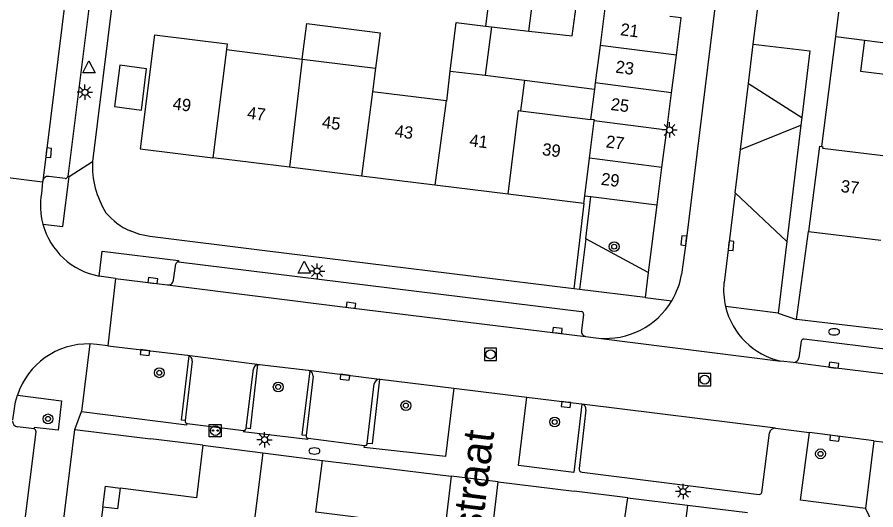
# Model space of a CAD drawing. Extents: x 131000 to 133014, y 396499 to 399001.
# Drawn here: x 131752.2 to 131822, y 397186.5 to 397226.6 of the extents above; entities that cross this region are included whole.
import ezdxf

# ---------------------------------------------------------------- set-up
doc = ezdxf.new("R2010")
doc.units = 0
for name, color, linetype in [('gg-afsc-erfafscheiding', 7, 'Continuous'), ('gg-afsc-muur', 7, 'Continuous'), ('gg-anno-huisnummerreeks BGT', 7, 'Continuous'), ('gg-anno-openbare ruimte label', 7, 'Continuous'), ('gg-bbg-bijgebouw', 7, 'Continuous'), ('gg-bbg-gedigitaliseerde bebouwing', 7, 'Continuous'), ('gg-bbg-gedigitaliseerde bijgebouw', 7, 'Continuous'), ('gg-bbg-hoofdgebouw', 7, 'Continuous'), ('gg-bbg-luifel en loopbrug', 7, 'Continuous'), ('gg-bbg-tussenscheiding', 7, 'Continuous'), ('gg-knt-verharding', 7, 'Continuous'), ('gg-knt-verharding nz', 7, 'Continuous'), ('gt-grn-groengrens', 7, 'Continuous'), ('gt-grn-weggrens', 7, 'Continuous'), ('gt-symb-boom', 7, 'Continuous'), ('gt-symb-brandkraan', 7, 'Continuous'), ('gt-symb-kolk', 7, 'Continuous'), ('gt-symb-laadpunt elektrisch vervoer', 7, 'Continuous'), ('gt-symb-lichtmast', 7, 'Continuous'), ('gt-symb-rioolschacht', 7, 'Continuous'), ('gt-symb-waterafsluiter', 7, 'Continuous')]:
    doc.layers.add(name, color=color, linetype=linetype)

# ---------------------------------------------------------------- blocks, each defined once
blk = doc.blocks.new('gt0-LMAST')
at = {"layer": 'gt-symb-lichtmast'}
for p, q in [((-0.182, 0.173), (-0.447, 0.438)), ((-0.005, 0.246), (-0.005, 0.621)), ((0.172, 0.173), (0.437, 0.438)), ((-0.255, -0.004), (-0.63, -0.004)), ((-0.182, -0.181), (-0.447, -0.446)), ((-0.005, -0.254), (-0.005, -0.629)), ((0.437, -0.446), (0.172, -0.181)), ((0.245, -0.004), (0.62, -0.004))]:
    blk.add_line(p, q, dxfattribs=at)
blk.add_circle((-0.005, -0.004), 0.25, dxfattribs=at)
blk = doc.blocks.new('gt0-BOOM')
at = {"layer": 'gt-symb-boom'}
for radius in [0.4, 0.2]:
    blk.add_circle((0, 0), radius, dxfattribs=at)
blk = doc.blocks.new('gt0-KOLK')
at = {"layer": 'gt-symb-kolk'}
blk.add_lwpolyline([(0, 0), (0.375, 0), (0.375, 0.4), (-0.375, 0.4), (-0.375, 0), (0, 0)], dxfattribs=at)
blk = doc.blocks.new('gt0-WAFSL')
at = {"layer": 'gt-symb-waterafsluiter'}
for p, q in [((-0.5, -0.333), (0, 0.667)), ((0, 0.667), (0.5, -0.333)), ((0.5, -0.333), (-0.5, -0.333))]:
    blk.add_line(p, q, dxfattribs=at)
blk = doc.blocks.new('gt0-BR')
at = {"layer": 'gt-symb-brandkraan'}
for centre, radius, start, end in [((-0.244, 0), 0.206, 107.56694, 252.43307), ((0.599, -2.664), 3, 106.89205, 107.56694), ((0, -0.691), 0.938, 73.10799, 106.89205), ((-0.599, -2.664), 3, 72.43309, 73.10799), ((0.244, 0), 0.206, 287.56695, 72.43309), ((0.599, 2.664), 3, 252.43307, 253.10797), ((0, 0.691), 0.938, 253.10797, 286.89206), ((-0.599, 2.664), 3, 286.89206, 287.56695)]:
    blk.add_arc(centre, radius, start, end, dxfattribs=at)
blk = doc.blocks.new('gt0-RS')
at = {"layer": 'gt-symb-rioolschacht'}
blk.add_lwpolyline([(-0.5, -0.5), (0.5, -0.5), (0.5, 0.5), (-0.5, 0.5)], close=True, dxfattribs=at)
blk.add_circle((0, 0), 0.375, dxfattribs=at)
blk = doc.blocks.new('gt0-LEV')
at = {"layer": 'gt-symb-laadpunt elektrisch vervoer'}
blk.add_lwpolyline([(-0.486, 0.501), (0.486, 0.501), (0.486, -0.499), (-0.486, -0.499)], close=True, dxfattribs=at)
for centre, radius in [((0, 0), 0.393), ((-0.186, 0), 0.0566), ((0.186, 0), 0.0566)]:
    blk.add_circle(centre, radius, dxfattribs=at)

msp = doc.modelspace()

# ---------------------------------------------------------------- linework, layer by layer
at = {"layer": 'gg-afsc-erfafscheiding'}
for p, q in [((131755.841, 397184.423), (131756.9, 397193.04)), ((131756.9, 397193.04), (131763.042, 397192.285)), ((131781.308, 397190.005), (131787.51, 397189.25)), ((131787.51, 397189.25), (131786.966, 397184.698)), ((131789.761, 397175.826), (131791.33, 397188.77)), ((131791.33, 397188.77), (131797.503, 397188.017))]:
    msp.add_line(p, q, dxfattribs=at)
at = {"layer": 'gg-afsc-muur'}
for p, q in [((131817.644, 397216.073), (131818.795, 397225.028)), ((131818.795, 397225.028), (131821.111, 397224.728)), ((131767.31, 397191.76), (131763.042, 397192.285)), ((131777.04, 397190.53), (131781.308, 397190.005)), ((131801.87, 397187.48), (131797.503, 397188.017))]:
    msp.add_line(p, q, dxfattribs=at)
at = {"layer": 'gg-bbg-bijgebouw'}
for p, q in [((131797.352, 397225.082), (131797.669, 397227.482)), ((131821.111, 397224.728), (131820.795, 397222.219)), ((131821.111, 397224.728), (131824.661, 397224.291))]:
    msp.add_line(p, q, dxfattribs=at)
at = {"layer": 'gg-bbg-gedigitaliseerde bebouwing'}
for p, q in [((131769.22, 397223.97), (131775.392, 397223.196)), ((131775.392, 397223.196), (131781.353, 397222.449)), ((131781.353, 397222.449), (131781.114, 397220.538)), ((131787.094, 397219.788), (131781.114, 397220.538)), ((131787.143, 397219.783), (131787.094, 397219.788))]:
    msp.add_line(p, q, dxfattribs=at)
msp.add_lwpolyline([(131763.38, 397225.17), (131769.277, 397224.433), (131769.22, 397223.97)], dxfattribs=at)
at = {"layer": 'gg-bbg-gedigitaliseerde bijgebouw'}
for p, q in [((131790.62, 397228.473), (131790.295, 397225.882)), ((131790.295, 397225.882), (131790.775, 397225.828)), ((131790.775, 397225.828), (131793.83, 397225.481)), ((131793.83, 397225.481), (131797.352, 397225.082)), ((131820.795, 397222.219), (131824.352, 397221.781))]:
    msp.add_line(p, q, dxfattribs=at)
msp.add_lwpolyline([(131762.309, 397219.045), (131762.738, 397222.415), (131760.561, 397222.693), (131760.132, 397219.323), (131762.309, 397219.045)], dxfattribs=at)
at = {"layer": 'gg-bbg-hoofdgebouw'}
for p, q in [((131800.011, 397227.348), (131799.619, 397224.305)), ((131806.219, 397226.548), (131805.279, 397226.669)), ((131805.827, 397223.505), (131806.219, 397226.548)), ((131799.619, 397224.305), (131799.227, 397221.261)), ((131805.435, 397220.461), (131805.827, 397223.505)), ((131787.143, 397219.783), (131787.414, 397222.225)), ((131787.414, 397222.225), (131790.271, 397221.874)), ((131790.271, 397221.874), (131793.467, 397221.481)), ((131793.467, 397221.481), (131793.146, 397218.985)), ((131799.227, 397221.261), (131799.162, 397220.755)), ((131799.162, 397220.755), (131798.842, 397218.277)), ((131805.042, 397217.418), (131805.435, 397220.461)), ((131793.146, 397218.985), (131798.842, 397218.277)), ((131804.65, 397214.374), (131805.042, 397217.418)), ((131817.45, 397216.098), (131816.58, 397209.17)), ((131817.45, 397216.098), (131817.644, 397216.073)), ((131774.358, 397214.39), (131768.117, 397215.161)), ((131780.208, 397213.666), (131774.358, 397214.39)), ((131804.258, 397211.331), (131804.65, 397214.374)), ((131786.187, 397212.927), (131780.208, 397213.666)), ((131792.147, 397212.191), (131786.187, 397212.927)), ((131798.3, 397211.43), (131792.147, 397212.191)), ((131798.3, 397211.43), (131798.38, 397212.07)), ((131798.38, 397212.07), (131798.877, 397212.008)), ((131798.877, 397212.008), (131804.223, 397211.335)), ((131804.223, 397211.335), (131804.258, 397211.331)), ((131816.58, 397209.17), (131822.45, 397208.447)), ((131767.31, 397191.76), (131772.175, 397191.145)), ((131772.175, 397191.145), (131777.04, 397190.53)), ((131801.87, 397187.48), (131806.735, 397186.88)), ((131759.17, 397186.72), (131758.844, 397184.128)), ((131806.735, 397186.88), (131811.6, 397186.28))]:
    msp.add_line(p, q, dxfattribs=at)
for points in [[(131763.38, 397225.17), (131762.22, 397215.89), (131768.117, 397215.161)], [(131817.644, 397216.073), (131817.722, 397216.063), (131817.709, 397215.956), (131823.299, 397215.266)], [(131767.31, 397191.76), (131766.78, 397187.49), (131760.57, 397188.27)], [(131782.77, 397185.53), (131776.51, 397186.32), (131777.04, 397190.53)], [(131760.57, 397188.27), (131760.36, 397186.57), (131759.17, 397186.72)], [(131795.1, 397184.01), (131801.25, 397183.25), (131801.87, 397187.48)]]:
    msp.add_lwpolyline(points, dxfattribs=at)
at = {"layer": 'gg-bbg-luifel en loopbrug'}
for p, q in [((131790.775, 397225.828), (131790.271, 397221.874)), ((131793.467, 397221.481), (131799.162, 397220.755))]:
    msp.add_line(p, q, dxfattribs=at)
for points in [[(131775.392, 397223.196), (131775.76, 397226.082), (131781.719, 397225.323), (131781.353, 397222.449)], [(131787.414, 397222.225), (131787.919, 397226.185), (131790.295, 397225.882)], [(131759.17, 397186.72), (131759.384, 397188.419), (131760.57, 397188.27)]]:
    msp.add_lwpolyline(points, dxfattribs=at)
at = {"layer": 'gg-bbg-tussenscheiding'}
for p, q in [((131793.83, 397225.481), (131794.15, 397228.031)), ((131769.22, 397223.97), (131768.117, 397215.161)), ((131805.827, 397223.505), (131799.619, 397224.305)), ((131775.392, 397223.196), (131774.358, 397214.39)), ((131805.435, 397220.461), (131799.227, 397221.261)), ((131781.114, 397220.538), (131780.208, 397213.666)), ((131787.094, 397219.788), (131786.187, 397212.927)), ((131798.765, 397215.133), (131799.148, 397218.177)), ((131805.042, 397217.418), (131799.148, 397218.177)), ((131798.38, 397212.07), (131798.765, 397215.133)), ((131804.65, 397214.374), (131798.765, 397215.133)), ((131772.175, 397191.145), (131771.117, 397182.569)), ((131806.735, 397186.88), (131805.672, 397178.327))]:
    msp.add_line(p, q, dxfattribs=at)
for points in [[(131792.147, 397212.191), (131792.992, 397219.004), (131793.146, 397218.985)], [(131799.148, 397218.177), (131799.155, 397218.238), (131798.842, 397218.277)]]:
    msp.add_lwpolyline(points, dxfattribs=at)
at = {"layer": 'gg-knt-verharding'}
for p, q in [((131760.493, 397232.282), (131758.333, 397214.867)), ((131758.562, 397231.547), (131756.324, 397213.643)), ((131811.683, 397221.202), (131812.077, 397224.416)), ((131811.026, 397215.841), (131811.683, 397221.202)), ((131816.019, 397218.431), (131815.946, 397217.826)), ((131815.946, 397217.826), (131814.804, 397208.347)), ((131810.593, 397212.309), (131811.026, 397215.841)), ((131748.783, 397213.872), (131754.277, 397213.202)), ((131754.288, 397213.286), (131754.277, 397213.202)), ((131756.116, 397213.481), (131754.774, 397213.644)), ((131756.432, 397213.629), (131756.324, 397213.643)), ((131754.277, 397213.202), (131754.176, 397212.255)), ((131810.593, 397212.309), (131809.695, 397204.996)), ((131798.3, 397211.43), (131797.48, 397204.5)), ((131804.223, 397211.335), (131803.529, 397205.827)), ((131815.58, 397201.99), (131816.58, 397209.17)), ((131814.804, 397208.347), (131814.101, 397202.505)), ((131764.92, 397205.19), (131765.116, 397206.521)), ((131765.329, 397206.701), (131798.1, 397202.647)), ((131803.529, 397205.827), (131803.277, 397203.785)), ((131760.217, 397205.346), (131758.874, 397205.527)), ((131760.217, 397205.346), (131759.57, 397199.859)), ((131760.217, 397205.346), (131764.438, 397204.81)), ((131797.936, 397204.444), (131797.48, 397204.5)), ((131803.277, 397203.785), (131797.936, 397204.444)), ((131814.101, 397202.505), (131809.822, 397203.044)), ((131798.27, 397202.417), (131798.1, 397201.088)), ((131851.75, 397197.76), (131815.58, 397201.99)), ((131758.122, 397200.004), (131757.438, 397194.509)), ((131798.425, 397200.621), (131799.484, 397200.479)), ((131815.981, 397200.223), (131815.79, 397198.886)), ((131848.037, 397196.445), (131816.213, 397200.389)), ((131759.57, 397199.859), (131766.05, 397199.096)), ((131766.45, 397198.615), (131765.872, 397193.769)), ((131766.05, 397199.096), (131766.208, 397199.043)), ((131815.312, 397198.494), (131814.315, 397198.615)), ((131770.824, 397193.136), (131771.428, 397197.966)), ((131771.764, 397198.338), (131771.91, 397198.345)), ((131771.91, 397198.345), (131775.872, 397197.874)), ((131776.274, 397197.379), (131775.698, 397192.539)), ((131775.872, 397197.874), (131776.028, 397197.822)), ((131780.681, 397191.912), (131781.233, 397196.755)), ((131787.715, 397196.4), (131793.665, 397195.668)), ((131798.465, 397194.63), (131797.922, 397189.872)), ((131753.58, 397193.102), (131752.228, 397193.257)), ((131766.021, 397193.527), (131770.608, 397192.947)), ((131813.879, 397193.151), (131816.638, 397192.796)), ((131750.152, 397164.03), (131753.744, 397192.853)), ((131775.868, 397192.322), (131780.457, 397191.741)), ((131812.771, 397187.919), (131813.393, 397192.76)), ((131821.893, 397192.131), (131816.638, 397192.796)), ((131821.893, 397192.131), (131821.202, 397186.616)), ((131821.893, 397192.131), (131827.009, 397191.489)), ((131798.163, 397189.554), (131812.56, 397187.758))]:
    msp.add_line(p, q, dxfattribs=at)
for points in [[(131809.227, 397229.593), (131806.623, 397208.399), (131806.25, 397205.671)], [(131812.077, 397224.416), (131812.655, 397229.14), (131812.656, 397229.144)], [(131812.077, 397224.416), (131816.674, 397223.87), (131816.019, 397218.431)], [(131754.298, 397209.764), (131755.909, 397209.555), (131756.432, 397213.629)], [(131797.48, 397204.5), (131772.341, 397207.599), (131763, 397208.75), (131762.175, 397208.915), (131761.385, 397209.203)], [(131758.874, 397205.527), (131759.11, 397207.56), (131765.341, 397206.798), (131765.329, 397206.701)], [(131759.57, 397199.859), (131758.682, 397199.964), (131758.122, 397200.004)], [(131765.872, 397193.769), (131765.579, 397193.804), (131766.208, 397199.043)], [(131771.764, 397198.338), (131771.143, 397193.098), (131770.824, 397193.136)], [(131775.698, 397192.539), (131775.399, 397192.575), (131776.028, 397197.822)], [(131781.684, 397197.139), (131781.089, 397191.866), (131780.681, 397191.912)], [(131781.684, 397197.139), (131781.735, 397197.136), (131787.715, 397196.4)], [(131751.843, 397193.824), (131751.978, 397194.749), (131752.077, 397195.302), (131752.227, 397195.843)], [(131752.227, 397195.843), (131755.807, 397195.378), (131755.554, 397192.992), (131753.591, 397193.199), (131753.58, 397193.102)], [(131787.715, 397196.4), (131787.03, 397190.838), (131780.44, 397191.589), (131780.457, 397191.741)], [(131798.136, 397195.116), (131797.476, 397189.55), (131792.981, 397190.106), (131793.665, 397195.668)], [(131793.665, 397195.668), (131798.096, 397195.123), (131798.136, 397195.116)], [(131757.438, 397194.509), (131766.009, 397193.43), (131766.021, 397193.527)], [(131770.608, 397192.947), (131770.6, 397192.878), (131775.859, 397192.248), (131775.868, 397192.322)], [(131821.202, 397186.616), (131815.929, 397187.288), (131816.638, 397192.796)]]:
    msp.add_lwpolyline(points, dxfattribs=at)
for centre, radius, start, end in [((131765.524, 397214.523), 7.199, 177.26186, 212.16855), ((131754.714, 397213.216), 0.432, 82.02931, 170.72331), ((131756.141, 397213.664), 0.184, 262.29692, 353.52929), ((131759.958, 397211.29), 5.862, 170.52282, 195.08497), ((131763.681, 397214.251), 5.545, 219.9477, 245.53806), ((131759.961, 397211.29), 5.865, 195.08405, 259.32164), ((131765.341, 397206.471), 0.23, 92.97123, 167.4291), ((131800.054, 397206.744), 6.288, 329.1228, 350.17376), ((131764.49, 397205.239), 0.432, 263.04042, 353.46279), ((131815.563, 397204.398), 5.899, 174.17807, 193.26693), ((131800.05, 397206.747), 6.293, 264.84161, 329.12273), ((131815.59, 397204.402), 5.926, 193.24901, 257.57298), ((131798.099, 397202.468), 0.179, 343.40552, 89.53295), ((131798.5, 397201.02), 0.406, 170.33918, 259.33136), ((131757.977, 397193.954), 6.052, 88.62289, 161.81001), ((131816.186, 397200.181), 0.21, 82.69129, 168.47745), ((131765.983, 397198.633), 0.468, 357.7687, 61.20072), ((131815.346, 397198.939), 0.447, 265.57499, 353.13425), ((131771.855, 397197.918), 0.429, 102.20717, 173.61451), ((131775.8, 397197.405), 0.475, 356.81948, 61.26776), ((131781.707, 397196.655), 0.485, 92.75836, 168.06652), ((131798.04, 397194.696), 0.43, 351.11962, 77.07283), ((131752.33, 397193.745), 0.498, 179.63699, 258.13656), ((131766.069, 397193.723), 0.202, 166.93312, 256.3083), ((131753.464, 397192.847), 0.28, 1.19737, 65.54319), ((131770.639, 397193.129), 0.185, 260.2822, 2.08965), ((131813.871, 397192.664), 0.487, 89.03865, 168.59657), ((131775.892, 397192.516), 0.195, 173.1411, 263.00992), ((131780.503, 397191.913), 0.178, 255.04641, 359.6693), ((131798.189, 397189.824), 0.271, 169.8404, 264.47378), ((131812.583, 397187.947), 0.19, 263.13507, 351.5546)]:
    msp.add_arc(centre, radius, start, end, dxfattribs=at)
at = {"layer": 'gg-knt-verharding nz'}
for p, q in [((131756.665, 397232.415), (131754.288, 397213.286)), ((131766.05, 397199.096), (131771.91, 397198.345)), ((131775.872, 397197.874), (131781.684, 397197.139)), ((131813.879, 397193.151), (131798.136, 397195.116))]:
    msp.add_line(p, q, dxfattribs=at)
for points in [[(131819, 397227.02), (131818.751, 397225.034), (131818.795, 397225.028)], [(131764.438, 397204.81), (131779.336, 397202.957), (131798.425, 397200.621)], [(131848.404, 397194.374), (131835.663, 397195.97), (131818.606, 397198.073), (131815.312, 397198.494)]]:
    msp.add_lwpolyline(points, dxfattribs=at)
at = {"layer": 'gt-grn-groengrens'}
for p, q in [((131811.683, 397221.202), (131816.019, 397218.431)), ((131811.026, 397215.841), (131815.946, 397217.826)), ((131798.445, 397208.572), (131798.877, 397212.008)), ((131814.804, 397208.347), (131810.593, 397212.309)), ((131798.445, 397208.572), (131797.936, 397204.444)), ((131803.529, 397205.827), (131798.445, 397208.572))]:
    msp.add_line(p, q, dxfattribs=at)
at = {"layer": 'gt-grn-weggrens'}
for p, q in [((131756.432, 397213.629), (131758.333, 397214.867)), ((131803.277, 397203.785), (131805.451, 397203.517)), ((131814.101, 397202.505), (131815.58, 397201.99)), ((131799.484, 397200.479), (131814.315, 397198.615)), ((131756.9, 397193.04), (131757.438, 397194.509)), ((131791.33, 397188.77), (131787.51, 397189.25)), ((131821.202, 397186.616), (131822, 397184.96))]:
    msp.add_line(p, q, dxfattribs=at)

# ---------------------------------------------------------------- block references
at = {"layer": 'gt-symb-boom'}
for p in [(131800.762, 397207.93), (131763.768, 397197.66), (131773.437, 397196.507), (131783.82, 397194.99), (131754.713, 397193.904), (131795.92, 397193.649), (131817.542, 397191.062)]:
    msp.add_blockref('gt0-BOOM', p, dxfattribs=at)
at = {"layer": 'gt-symb-brandkraan'}
for p in [(131818.649, 397200.993), (131776.382, 397191.288)]:
    msp.add_blockref('gt0-BR', p, dxfattribs=at)
at = {"layer": 'gt-symb-kolk'}
for p, rotation in [((131754.574, 397215.595), -95.99886832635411), ((131806.623, 397208.399), 84.00113167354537), ((131810.068, 397208.019), -95.99886832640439), ((131763.214, 397204.965), -6.997895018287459), ((131779.336, 397202.957), -6.9978950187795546), ((131796.121, 397200.903), -6.9978950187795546), ((131762.627, 397199.499), 173.00210498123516), ((131818.606, 397198.073), -6.997895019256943), ((131778.888, 397197.492), 173.0021049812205), ((131796.871, 397195.273), 173.00210498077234), ((131818.714, 397192.529), 173.0021049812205)]:
    msp.add_blockref('gt0-KOLK', p, dxfattribs=dict(at, rotation=rotation))
at = {"layer": 'gt-symb-laadpunt elektrisch vervoer'}
msp.add_blockref('gt0-LEV', (131768.321, 397192.954), dxfattribs=at)
at = {"layer": 'gt-symb-lichtmast'}
for p in [(131757.72, 397220.495), (131805.269, 397217.432), (131776.604, 397205.945), (131772.331, 397192.215), (131806.375, 397187.986)]:
    msp.add_blockref('gt0-LMAST', p, dxfattribs=at)
at = {"layer": 'gt-symb-rioolschacht'}
for p in [(131790.704, 397199.155), (131808.127, 397197.094)]:
    msp.add_blockref('gt0-RS', p, dxfattribs=at)
at = {"layer": 'gt-symb-waterafsluiter'}
for p in [(131758.041, 397222.399), (131775.552, 397206.089)]:
    msp.add_blockref('gt0-WAFSL', p, dxfattribs=at)

# ---------------------------------------------------------------- texts
at = {"layer": 'gg-anno-huisnummerreeks BGT'}
for s, rotation, p in [('21', 352.7, (131801.221, 397225.141)), ('23', 352.7, (131800.829, 397222.097)), ('49', 352.9, (131764.809, 397219.097)), ('25', 352.6, (131800.437, 397219.056)), ('47', 352.9, (131770.873, 397218.348)), ('45', 352.9, (131776.96, 397217.595)), ('43', 352.9, (131782.874, 397216.864)), ('41', 352.9, (131788.949, 397216.113)), ('27', 352.7, (131800.044, 397216.01)), ('39', 352.9, (131794.864, 397215.382)), ('29', 352.7, (131799.652, 397212.967)), ('37', 353, (131819.15, 397212.38))]:
    msp.add_text(s, height=1, rotation=rotation, dxfattribs=at).set_placement(p)
at = {"layer": 'gg-anno-openbare ruimte label'}
msp.add_text('Abdij van Egmondstraat', height=2.5, rotation=82.9, dxfattribs=at).set_placement((131786.623, 397157.603))

doc.saveas('drawing.dxf')
